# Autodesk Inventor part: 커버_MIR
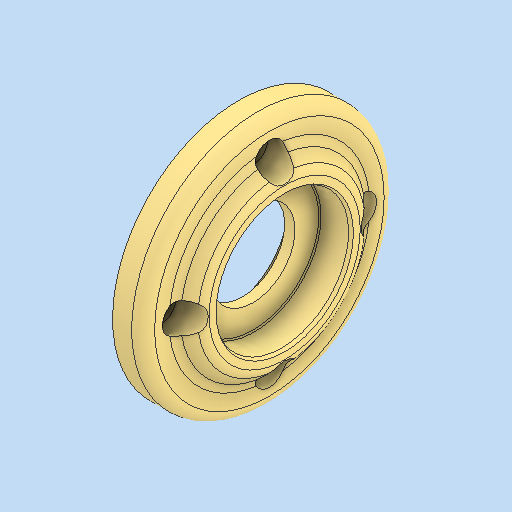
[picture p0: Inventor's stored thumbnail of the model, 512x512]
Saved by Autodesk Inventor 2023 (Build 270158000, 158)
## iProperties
Created: 2026-06
Part Number: 커버_MIR
Material: 알루미늄 6061
Document SubType Name: Modeling
Designer: home
Density: 2.7 g/cm^3
Appearance: 기본값
Author: jhkim
Sending System: Autodesk Inventor 2027
Preprocessor: ST-DEVELOPER v20.1
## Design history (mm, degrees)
derived "커버.ipt"
feature "솔리드2::커버.ipt" dims "d0" = 10
tag "피쳐 태그1"
node "솔리드2"
